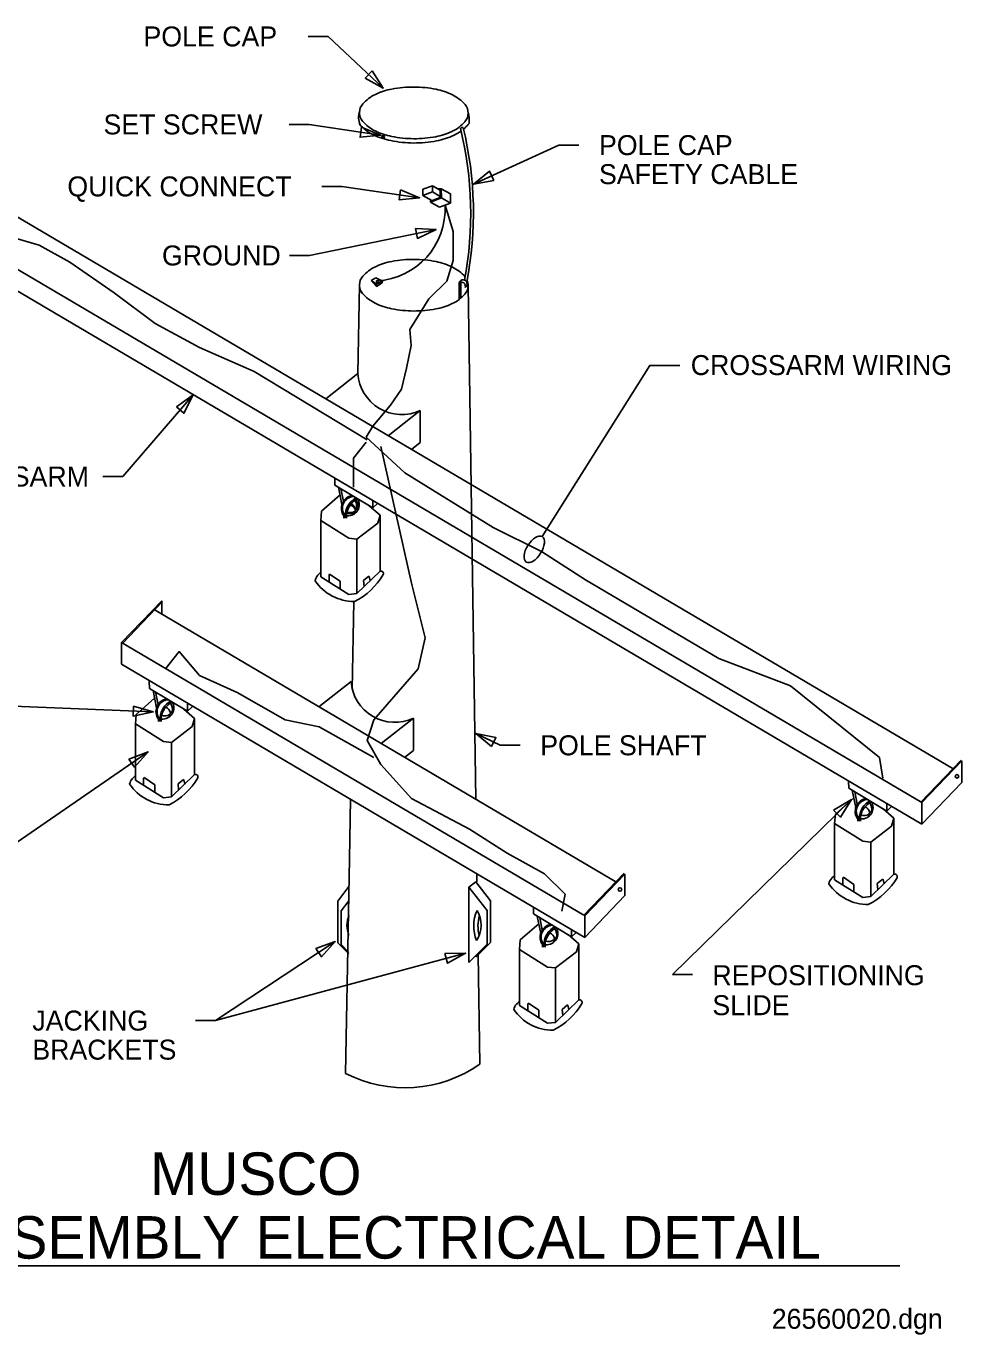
# Model space of a CAD drawing. Extents: x 10378 to 10425.2, y 10088.7 to 10132.4.
# Drawn here: x 10393.97 to 10425.18, y 10088.71 to 10132.38 of the extents above; entities that cross this region are included whole.
import ezdxf

# ---------------------------------------------------------------- set-up
doc = ezdxf.new("R2010")
doc.units = 0
for name, color, linetype in [('G-ANNO-TEXT', 7, 'Continuous'), ('G-DETL-LINE', 7, 'Continuous'), ('G-DETL-OTLN', 7, 'Continuous'), ('G-DETL-PATT', 7, 'Continuous')]:
    doc.layers.add(name, color=color, linetype=linetype)

msp = doc.modelspace()

# ---------------------------------------------------------------- linework, layer by layer
at = {"layer": 'G-ANNO-TEXT'}
for p, q in [((10403.381, 10132.033), (10404.048, 10132.033)), ((10404.048, 10132.033), (10405.885, 10130.313)), ((10402.741, 10129.099), (10403.408, 10129.099)), ((10403.408, 10129.099), (10405.796, 10128.737)), ((10411.744, 10128.407), (10408.893, 10127.106)), ((10412.411, 10128.407), (10411.744, 10128.407)), ((10403.834, 10127.03), (10404.501, 10127.03)), ((10404.501, 10127.03), (10407.097, 10126.652)), ((10403.427, 10124.727), (10407.645, 10125.592)), ((10402.76, 10124.727), (10403.427, 10124.727)), ((10397.193, 10117.35), (10399.546, 10120.075)), ((10396.526, 10117.35), (10397.193, 10117.35)), ((10391.793, 10109.759), (10398.213, 10109.494)), ((10409.785, 10108.382), (10408.966, 10108.778)), ((10410.452, 10108.382), (10409.785, 10108.382)), ((10393.168, 10104.808), (10398.04, 10108.165)), ((10415.527, 10100.733), (10421.497, 10106.57)), ((10400.289, 10099.197), (10404.282, 10101.835)), ((10400.289, 10099.197), (10408.629, 10101.444)), ((10416.194, 10100.733), (10415.527, 10100.733)), ((10399.622, 10099.197), (10400.289, 10099.197)), ((10399.622, 10099.197), (10400.289, 10099.197)), ((10380.467, 10091.02), (10423.113, 10091.02))]:
    msp.add_line(p, q, dxfattribs=at)
for points in [[(10405.512, 10130.891), (10405.885, 10130.313), (10405.284, 10130.647)], [(10405.161, 10129.002), (10405.796, 10128.737), (10405.112, 10128.672)], [(10409.569, 10127.231), (10408.893, 10127.106), (10409.43, 10127.535)], [(10406.462, 10126.913), (10407.097, 10126.652), (10406.413, 10126.583)], [(10406.959, 10125.621), (10407.645, 10125.592), (10407.025, 10125.295)], [(10398.984, 10119.68), (10399.546, 10120.075), (10399.236, 10119.462)], [(10397.554, 10109.688), (10398.213, 10109.494), (10397.54, 10109.355)], [(10409.494, 10108.338), (10408.966, 10108.778), (10409.639, 10108.638)], [(10397.397, 10107.924), (10398.04, 10108.165), (10397.586, 10107.649)], [(10420.903, 10106.223), (10421.497, 10106.57), (10421.136, 10105.985)], [(10403.634, 10101.607), (10404.282, 10101.835), (10403.818, 10101.329)], [(10407.941, 10101.431), (10408.629, 10101.444), (10408.028, 10101.11)]]:
    msp.add_lwpolyline(points, close=True, dxfattribs=at)
msp.add_lwpolyline([(10415.778, 10121.059), (10414.778, 10121.059), (10411.186, 10115.344)], dxfattribs=at)
msp.add_ellipse((10410.92, 10114.921), major_axis=(-0.266, -0.423), ratio=0.5, dxfattribs=at)
at = {"layer": 'G-DETL-LINE'}
for p, q in [((10407.521, 10127.05), (10407.202, 10126.936)), ((10407.781, 10126.902), (10407.521, 10127.05)), ((10407.521, 10126.845), (10407.521, 10127.05)), ((10407.202, 10126.936), (10407.202, 10126.731)), ((10407.521, 10126.845), (10407.202, 10126.731)), ((10407.506, 10126.557), (10407.202, 10126.731)), ((10407.456, 10126.538), (10407.783, 10126.661)), ((10407.456, 10126.509), (10407.821, 10126.647)), ((10407.456, 10126.509), (10407.456, 10126.586)), ((10407.783, 10126.695), (10407.521, 10126.845)), ((10407.679, 10126.951), (10407.818, 10126.951)), ((10407.783, 10126.661), (10407.78, 10126.951)), ((10408.122, 10126.777), (10407.818, 10126.951)), ((10407.821, 10126.647), (10407.818, 10126.951)), ((10408.126, 10126.473), (10407.821, 10126.647)), ((10408.122, 10126.777), (10408.126, 10126.473)), ((10407.76, 10126.335), (10407.456, 10126.509)), ((10408.126, 10126.473), (10407.76, 10126.335)), ((10405.485, 10123.888), (10405.63, 10123.978)), ((10405.63, 10123.978), (10405.853, 10123.866)), ((10405.652, 10123.688), (10405.485, 10123.888)), ((10405.652, 10123.766), (10405.485, 10123.888)), ((10405.853, 10123.866), (10405.652, 10123.766)), ((10405.652, 10123.688), (10405.842, 10123.81)), ((10405.652, 10123.766), (10405.652, 10123.688)), ((10405.842, 10123.81), (10405.853, 10123.866)), ((10404.265, 10117.292), (10404.27, 10117.063)), ((10404.27, 10117.063), (10405.54, 10116.301)), ((10404.39, 10116.991), (10404.506, 10116.416)), ((10404.473, 10116.941), (10404.557, 10116.526)), ((10404.441, 10116.738), (10403.827, 10116.2)), ((10405.54, 10116.301), (10405.54, 10116.539)), ((10403.827, 10116.2), (10403.8, 10115.879)), ((10404.624, 10116.106), (10404.66, 10116.118)), ((10404.624, 10115.961), (10404.624, 10116.106)), ((10404.66, 10115.961), (10404.66, 10116.118)), ((10405.778, 10116.066), (10405.418, 10116.373)), ((10405.54, 10116.301), (10405.694, 10116.448)), ((10405.698, 10115.798), (10405.778, 10116.066)), ((10405.778, 10116.066), (10405.778, 10114.193)), ((10403.8, 10115.879), (10403.8, 10114.006)), ((10403.8, 10115.879), (10404.736, 10115.29)), ((10404.57, 10116.034), (10404.606, 10116.046)), ((10404.57, 10115.961), (10404.57, 10116.034)), ((10404.606, 10115.961), (10404.606, 10116.046)), ((10405.003, 10115.263), (10405.698, 10115.798)), ((10404.736, 10115.29), (10405.003, 10115.263)), ((10405.003, 10115.263), (10405.003, 10113.444)), ((10403.8, 10114.006), (10404.736, 10113.418)), ((10404.095, 10114.09), (10404.074, 10114.066)), ((10404.074, 10113.834), (10404.074, 10114.066)), ((10404.095, 10114.09), (10404.446, 10113.854)), ((10405.778, 10114.193), (10405.003, 10113.444)), ((10405.224, 10113.879), (10405.404, 10114.029)), ((10405.243, 10113.685), (10405.224, 10113.879)), ((10405.404, 10114.029), (10405.415, 10114.019)), ((10405.415, 10114.019), (10405.448, 10113.874)), ((10404.446, 10113.603), (10404.446, 10113.854)), ((10405.003, 10113.444), (10404.736, 10113.418)), ((10398.079, 10110.507), (10398.084, 10110.279)), ((10398.255, 10109.953), (10397.641, 10109.415)), ((10398.084, 10110.279), (10399.354, 10109.517)), ((10398.204, 10110.207), (10398.32, 10109.632)), ((10398.287, 10110.157), (10398.371, 10109.741)), ((10399.592, 10109.281), (10399.232, 10109.589)), ((10399.354, 10109.517), (10399.354, 10109.755)), ((10399.354, 10109.517), (10399.508, 10109.664)), ((10397.641, 10109.415), (10397.614, 10109.094)), ((10397.614, 10109.094), (10398.55, 10108.506)), ((10397.614, 10109.094), (10397.614, 10107.222)), ((10398.384, 10109.25), (10398.42, 10109.261)), ((10398.384, 10109.176), (10398.384, 10109.25)), ((10398.42, 10109.176), (10398.42, 10109.261)), ((10398.438, 10109.321), (10398.473, 10109.333)), ((10398.438, 10109.176), (10398.438, 10109.321)), ((10398.473, 10109.176), (10398.473, 10109.333)), ((10399.512, 10109.014), (10399.592, 10109.281)), ((10399.592, 10109.281), (10399.592, 10107.409)), ((10398.817, 10108.479), (10399.512, 10109.014)), ((10398.55, 10108.506), (10398.817, 10108.479)), ((10398.817, 10108.479), (10398.817, 10106.66)), ((10399.592, 10107.409), (10398.817, 10106.66)), ((10397.614, 10107.222), (10398.55, 10106.633)), ((10397.909, 10107.306), (10397.888, 10107.281)), ((10397.888, 10107.049), (10397.888, 10107.281)), ((10397.909, 10107.306), (10398.26, 10107.069)), ((10398.26, 10106.818), (10398.26, 10107.069)), ((10399.038, 10107.095), (10399.218, 10107.244)), ((10399.057, 10106.901), (10399.038, 10107.095)), ((10399.218, 10107.244), (10399.229, 10107.234)), ((10399.229, 10107.234), (10399.261, 10107.09)), ((10421.403, 10107.181), (10421.408, 10106.953)), ((10421.408, 10106.953), (10422.678, 10106.19)), ((10398.817, 10106.66), (10398.55, 10106.633)), ((10421.579, 10106.627), (10420.965, 10106.089)), ((10421.527, 10106.881), (10421.644, 10106.305)), ((10421.611, 10106.831), (10421.695, 10106.415)), ((10420.965, 10106.089), (10420.938, 10105.768)), ((10422.916, 10105.955), (10422.556, 10106.263)), ((10422.678, 10106.19), (10422.678, 10106.429)), ((10422.678, 10106.19), (10422.832, 10106.338)), ((10420.938, 10105.768), (10420.938, 10103.896)), ((10420.938, 10105.768), (10421.874, 10105.179)), ((10421.708, 10105.923), (10421.744, 10105.935)), ((10421.708, 10105.85), (10421.708, 10105.923)), ((10421.744, 10105.85), (10421.744, 10105.935)), ((10421.762, 10105.995), (10421.797, 10106.007)), ((10421.762, 10105.85), (10421.762, 10105.995)), ((10421.797, 10105.85), (10421.797, 10106.007)), ((10422.141, 10105.153), (10422.836, 10105.688)), ((10422.836, 10105.688), (10422.916, 10105.955)), ((10422.916, 10105.955), (10422.916, 10104.083)), ((10421.874, 10105.179), (10422.141, 10105.153)), ((10422.141, 10105.153), (10422.141, 10103.334)), ((10420.938, 10103.896), (10421.874, 10103.307)), ((10421.233, 10103.98), (10421.212, 10103.955)), ((10421.212, 10103.723), (10421.212, 10103.955)), ((10421.233, 10103.98), (10421.584, 10103.743)), ((10422.916, 10104.083), (10422.141, 10103.334)), ((10422.362, 10103.768), (10422.542, 10103.918)), ((10422.542, 10103.918), (10422.553, 10103.908)), ((10422.553, 10103.908), (10422.585, 10103.763)), ((10404.736, 10103.667), (10404.364, 10103.181)), ((10408.742, 10103.653), (10408.97, 10103.828)), ((10408.742, 10103.653), (10409.344, 10102.868)), ((10408.742, 10101.14), (10408.742, 10103.653)), ((10408.97, 10103.828), (10409.458, 10103.191)), ((10421.584, 10103.492), (10421.584, 10103.743)), ((10422.381, 10103.575), (10422.362, 10103.768)), ((10404.364, 10103.181), (10404.364, 10101.793)), ((10404.736, 10103.195), (10404.478, 10102.858)), ((10409.458, 10103.191), (10409.458, 10101.803)), ((10410.892, 10102.983), (10410.897, 10102.755)), ((10422.141, 10103.334), (10421.874, 10103.307)), ((10404.478, 10102.858), (10404.478, 10101.733)), ((10409.344, 10102.868), (10409.344, 10101.742)), ((10410.897, 10102.755), (10412.167, 10101.992)), ((10411.017, 10102.683), (10411.134, 10102.107)), ((10411.1, 10102.633), (10411.185, 10102.217)), ((10411.068, 10102.429), (10410.454, 10101.891)), ((10412.167, 10101.992), (10412.167, 10102.231)), ((10412.167, 10101.992), (10412.321, 10102.14)), ((10404.364, 10101.793), (10404.736, 10101.421)), ((10404.478, 10101.733), (10404.736, 10101.474)), ((10409.344, 10101.742), (10408.742, 10101.14)), ((10409.458, 10101.803), (10408.97, 10101.315)), ((10410.454, 10101.891), (10410.427, 10101.57)), ((10411.197, 10101.725), (10411.233, 10101.737)), ((10411.197, 10101.652), (10411.197, 10101.725)), ((10411.233, 10101.652), (10411.233, 10101.737)), ((10411.251, 10101.797), (10411.287, 10101.809)), ((10411.251, 10101.652), (10411.251, 10101.797)), ((10411.287, 10101.652), (10411.287, 10101.809)), ((10412.405, 10101.757), (10412.045, 10102.065)), ((10412.325, 10101.49), (10412.405, 10101.757)), ((10412.405, 10101.757), (10412.405, 10099.885)), ((10410.427, 10101.57), (10410.427, 10099.698)), ((10410.427, 10101.57), (10411.363, 10100.982)), ((10411.63, 10100.955), (10412.325, 10101.49)), ((10411.363, 10100.982), (10411.63, 10100.955)), ((10411.63, 10100.955), (10411.63, 10099.136)), ((10410.427, 10099.698), (10411.363, 10099.109)), ((10410.723, 10099.782), (10410.701, 10099.757)), ((10410.701, 10099.525), (10410.701, 10099.757)), ((10410.723, 10099.782), (10411.073, 10099.545)), ((10411.073, 10099.294), (10411.073, 10099.545)), ((10412.405, 10099.885), (10411.63, 10099.136)), ((10411.851, 10099.57), (10412.031, 10099.72)), ((10411.87, 10099.377), (10411.851, 10099.57)), ((10412.031, 10099.72), (10412.043, 10099.71)), ((10412.043, 10099.71), (10412.075, 10099.565)), ((10411.63, 10099.136), (10411.363, 10099.109))]:
    msp.add_line(p, q, dxfattribs=at)
for centre, radius in [((10405.686, 10123.855), 0.0334), ((10425.018, 10107.347), 0.0592), ((10413.777, 10103.572), 0.0592)]:
    msp.add_circle(centre, radius, dxfattribs=at)
for centre, radius, start, end in [((10404.923, 10116.289), 0.436, 100.2717, 215.8313), ((10404.923, 10116.289), 0.4, 94.0056, 217.4608), ((10405.308, 10116.037), 0.688, 118.8543, 174.2368), ((10405.367, 10115.972), 0.722, 118.1089, 168.3754), ((10404.708, 10116.413), 0.375, 265.3953, 31.5556), ((10404.605, 10116.346), 0.395, 347.8326, 31.9067), ((10404.645, 10116.356), 0.395, 349.7008, 34.0489), ((10404.763, 10116.501), 0.356, 253.9647, 301.1435), ((10404.738, 10116.494), 0.382, 259.327, 302.5745), ((10404.69, 10116.131), 0.289, 20.663, 69.297), ((10404.694, 10116.186), 0.281, 12.7976, 63.9539), ((10405.076, 10116.162), 0.133, 95.1644, 192.366), ((10403.934, 10113.825), 0.328, 134.8398, 171.2692), ((10403.875, 10113.942), 0.207, 111.139, 146.0525), ((10403.878, 10115.265), 2.331, 296.6306, 329.3358), ((10405.803, 10114.11), 0.087, 337.3261, 106.4069), ((10404.912, 10114.752), 1.57, 213.9622, 270.399), ((10398.737, 10109.505), 0.436, 100.2717, 215.8313), ((10398.737, 10109.505), 0.4, 94.0056, 217.4608), ((10399.122, 10109.252), 0.688, 118.8543, 174.2368), ((10399.181, 10109.188), 0.722, 118.1089, 168.3754), ((10398.521, 10109.629), 0.375, 265.3953, 31.5556), ((10398.508, 10109.401), 0.281, 12.7976, 63.9539), ((10398.89, 10109.377), 0.133, 95.1644, 192.366), ((10398.459, 10109.571), 0.395, 349.7008, 34.0489), ((10398.577, 10109.716), 0.356, 253.9647, 301.1435), ((10397.689, 10107.157), 0.207, 111.139, 146.0525), ((10399.617, 10107.326), 0.087, 337.3261, 106.4069), ((10397.748, 10107.04), 0.328, 134.8398, 171.2692), ((10398.726, 10107.967), 1.57, 213.9622, 270.399), ((10397.692, 10108.481), 2.331, 296.6306, 329.3358), ((10422.061, 10106.178), 0.436, 100.2717, 215.8313), ((10422.061, 10106.178), 0.4, 94.0056, 217.4608), ((10422.446, 10105.926), 0.688, 118.8543, 174.2368), ((10422.505, 10105.862), 0.722, 118.1089, 168.3754), ((10421.845, 10106.302), 0.375, 265.3953, 31.5556), ((10421.783, 10106.245), 0.395, 349.7008, 34.0489), ((10421.901, 10106.39), 0.356, 253.9647, 301.1435), ((10421.832, 10106.075), 0.281, 12.7976, 63.9539), ((10422.214, 10106.051), 0.133, 95.1644, 192.366), ((10421.072, 10103.714), 0.328, 134.8398, 171.2692), ((10421.013, 10103.831), 0.207, 111.139, 146.0525), ((10421.016, 10105.154), 2.331, 296.6306, 329.3358), ((10422.941, 10103.999), 0.087, 337.3261, 106.4069), ((10422.05, 10104.641), 1.57, 213.9622, 270.399), ((10405.617, 10102.373), 0.945, 158.9471, 201.0529), ((10403.643, 10102.34), 1.136, 15.9016, 17.6825), ((10410.178, 10102.35), 1.279, 155.8022, 202.2608), ((10408.204, 10102.383), 0.945, 326.7536, 31.3094), ((10410.178, 10102.35), 1.136, 162.3175, 195.7456), ((10411.55, 10101.98), 0.436, 100.2717, 215.8313), ((10411.55, 10101.98), 0.4, 94.0056, 217.4608), ((10411.935, 10101.728), 0.688, 118.8543, 174.2368), ((10411.994, 10101.664), 0.722, 118.1089, 168.3754), ((10411.335, 10102.104), 0.375, 265.3953, 31.5556), ((10411.321, 10101.877), 0.281, 12.7976, 63.9539), ((10411.272, 10102.047), 0.395, 349.7008, 34.0489), ((10411.39, 10102.192), 0.356, 253.9647, 301.1435), ((10411.704, 10101.853), 0.133, 95.1644, 192.366), ((10410.562, 10099.516), 0.328, 134.8398, 171.2692), ((10411.539, 10100.443), 1.57, 213.9622, 270.399), ((10410.502, 10099.633), 0.207, 111.139, 149.3316), ((10410.505, 10100.957), 2.331, 296.6306, 329.3358), ((10412.43, 10099.801), 0.087, 337.3261, 106.4069)]:
    msp.add_arc(centre, radius, start, end, dxfattribs=at)
at = {"layer": 'G-DETL-OTLN'}
for p, q in [((10405.876, 10128.642), (10405.876, 10128.733)), ((10405.885, 10128.645), (10405.885, 10128.736)), ((10391.182, 10127.479), (10424.91, 10107.581)), ((10390.083, 10126.387), (10423.843, 10106.471)), ((10390.083, 10125.666), (10423.843, 10105.749)), ((10405.037, 10120.784), (10405.089, 10123.745)), ((10408.417, 10123.815), (10408.472, 10123.893)), ((10408.417, 10123.261), (10408.417, 10123.815)), ((10408.472, 10123.305), (10408.472, 10123.835)), ((10408.617, 10123.659), (10408.673, 10123.737)), ((10408.969, 10106.579), (10408.716, 10123.725)), ((10405.037, 10120.784), (10403.963, 10119.939)), ((10407.117, 10119.557), (10406.043, 10118.712)), ((10407.117, 10119.557), (10407.117, 10118.482)), ((10407.117, 10118.482), (10406.824, 10118.251)), ((10397.156, 10111.808), (10398.494, 10113.2)), ((10397.182, 10111.783), (10398.519, 10113.175)), ((10398.494, 10113.2), (10398.494, 10112.759)), ((10404.851, 10110.245), (10404.903, 10113.182)), ((10398.219, 10112.921), (10413.638, 10103.825)), ((10397.156, 10111.808), (10397.156, 10111.086)), ((10397.156, 10111.808), (10412.571, 10102.714)), ((10397.156, 10111.086), (10412.602, 10101.974)), ((10404.808, 10110.512), (10403.734, 10109.668)), ((10406.888, 10109.285), (10405.814, 10108.44)), ((10406.888, 10109.285), (10406.888, 10108.21)), ((10406.888, 10108.21), (10406.595, 10107.98)), ((10423.811, 10106.489), (10425.154, 10107.887)), ((10423.843, 10106.471), (10425.18, 10107.863)), ((10425.18, 10107.863), (10425.18, 10107.141)), ((10423.843, 10105.749), (10425.18, 10107.141)), ((10404.752, 10104.593), (10404.787, 10106.585)), ((10423.843, 10106.471), (10423.843, 10105.749)), ((10404.626, 10097.434), (10404.752, 10104.593)), ((10409.009, 10103.828), (10409.006, 10104.096)), ((10412.571, 10102.714), (10413.914, 10104.112)), ((10412.602, 10102.695), (10413.94, 10104.087)), ((10413.94, 10104.087), (10413.94, 10103.366)), ((10412.602, 10101.974), (10413.94, 10103.366)), ((10412.602, 10102.695), (10412.602, 10101.974)), ((10409.099, 10097.744), (10409.045, 10101.39))]:
    msp.add_line(p, q, dxfattribs=at)
msp.add_circle((10405.882, 10128.688), 0.0455, dxfattribs=at)
for centre, radius, start, end in [((10406.176, 10128.92), 1.303, 115.1068, 138.6129), ((10406.607, 10128.001), 2.319, 100.8241, 115.1068), ((10406.887, 10126.54), 3.806, 89.6877, 100.8241), ((10406.887, 10126.54), 3.806, 78.5514, 89.6877), ((10407.182, 10127.998), 2.319, 64.2687, 78.5514), ((10407.623, 10128.912), 1.303, 40.7626, 64.2687), ((10405.528, 10129.491), 0.439, 138.6129, 179.6877), ((10408.277, 10129.476), 0.439, 359.6877, 40.7626), ((10405.756, 10129.34), 0.694, 163.3529, 201.6942), ((10405.528, 10129.491), 0.439, 179.6877, 220.7626), ((10406.183, 10130.055), 1.303, 220.7626, 244.2687), ((10407.629, 10130.048), 1.303, 295.1068, 318.6129), ((10408.277, 10129.476), 0.439, 318.6129, 359.6877), ((10407.639, 10129.229), 1.11, 354.6742, 14.364), ((10406.183, 10130.055), 1.447, 220.7626, 244.2687), ((10406.623, 10130.97), 2.462, 244.2687, 258.5514), ((10406.623, 10130.97), 2.319, 244.2687, 258.5514), ((10407.198, 10130.967), 2.319, 280.8241, 295.1068), ((10407.198, 10130.967), 2.462, 280.8241, 295.1068), ((10407.629, 10130.048), 1.447, 295.1068, 306.0196), ((10408.522, 10128.905), 0.0895, 72.3491, 135.7413), ((10396.772, 10126.118), 12.028, 349.3877, 13.7065), ((10396.863, 10126.14), 12.028, 348.9395, 13.7065), ((10407.629, 10130.048), 1.447, 310.1185, 318.6129), ((10408.277, 10129.476), 0.583, 318.6129, 323.3443), ((10406.919, 10132.428), 3.95, 258.5514, 269.6877), ((10406.919, 10132.428), 3.806, 258.5514, 269.6877), ((10406.919, 10132.428), 3.95, 269.6877, 280.8241), ((10406.919, 10132.428), 3.806, 269.6877, 280.8241), ((10406.607, 10122.252), 2.319, 100.8241, 115.1068), ((10406.887, 10120.791), 3.806, 89.6877, 100.8241), ((10406.887, 10120.791), 3.806, 78.5514, 89.6877), ((10407.182, 10122.249), 2.319, 64.2687, 78.5514), ((10405.528, 10123.742), 0.439, 138.6129, 179.6877), ((10406.176, 10123.171), 1.303, 115.1068, 138.6129), ((10407.623, 10123.163), 1.303, 40.7626, 64.2687), ((10408.277, 10123.727), 0.439, 39.8709, 40.7626), ((10405.528, 10123.742), 0.439, 179.6877, 220.7626), ((10408.489, 10123.701), 0.135, 341.8936, 122.3019), ((10408.545, 10123.779), 0.135, 341.8936, 122.3019), ((10408.277, 10123.727), 0.439, 318.6129, 359.6877), ((10408.277, 10123.727), 0.439, 359.6877, 23.1028), ((10406.183, 10124.307), 1.303, 220.7626, 244.2687), ((10406.623, 10125.221), 2.319, 244.2687, 258.5514), ((10407.198, 10125.218), 2.319, 280.8241, 295.1068), ((10407.629, 10124.299), 1.303, 295.1068, 318.6129), ((10406.919, 10126.679), 3.806, 258.5514, 269.6877), ((10406.919, 10126.679), 3.806, 269.6877, 280.8241), ((10406.498, 10120.885), 1.465, 183.9415, 294.9806), ((10406.27, 10110.613), 1.465, 183.9415, 294.9806), ((10406.606, 10101.295), 4.339, 242.8489, 305.0763)]:
    msp.add_arc(centre, radius, start, end, dxfattribs=at)
at = {"layer": 'G-DETL-PATT'}
for points in [[(10407.943, 10126.404), (10408.212, 10125.529), (10408.212, 10124.563), (10407.998, 10123.865), (10407.408, 10123.275), (10406.764, 10122.255), (10406.818, 10121.718), (10406.657, 10120.967), (10406.496, 10120.269), (10406.121, 10119.733), (10405.531, 10119.035), (10405.316, 10118.659), (10406.603, 10117.478), (10409.553, 10115.654), (10411.162, 10114.849)], [(10405.342, 10118.577), (10401.582, 10120.857), (10399.759, 10121.655), (10398.278, 10122.453), (10396.911, 10123.479), (10395.43, 10124.505), (10394.404, 10125.075), (10393.607, 10125.303), (10393.151, 10125.417), (10392.354, 10125.417), (10392.012, 10125.303)], [(10405.316, 10118.498), (10404.887, 10117.961), (10404.887, 10117.478), (10404.887, 10116.995)], [(10405.798, 10118.349), (10406.823, 10113.789), (10407.279, 10111.965), (10407.051, 10110.939), (10405.57, 10109.229), (10405.342, 10108.545), (10405.798, 10107.747), (10406.823, 10106.607), (10408.76, 10105.581), (10410.013, 10104.783), (10411.266, 10104.099), (10411.95, 10103.415), (10411.836, 10102.845)], [(10411.162, 10114.849), (10412.633, 10113.903), (10417.077, 10111.281), (10419.469, 10110.369), (10422.432, 10107.975), (10422.546, 10107.291)], [(10405.57, 10107.975), (10403.747, 10109.001), (10402.607, 10109.229), (10401.012, 10110.141), (10399.759, 10110.711), (10399.076, 10111.509), (10398.62, 10110.939)]]:
    msp.add_lwpolyline(points, dxfattribs=at)
msp.add_arc((10405.543, 10126.279), 2.403, 273.178, 2.9796, dxfattribs=at)

# ---------------------------------------------------------------- texts
at = {"layer": 'G-ANNO-TEXT'}
for s, height, p in [('POLE CAP', 0.6667, (10397.885, 10131.7)), ('SET SCREW', 0.6667, (10396.552, 10128.765)), ('POLE CAP ', 0.6667, (10413.078, 10128.074)), ('SAFETY CABLE', 0.66667, (10413.078, 10127.106)), ('QUICK CONNECT', 0.66667, (10395.346, 10126.696)), ('GROUND', 0.6667, (10398.503, 10124.393)), ('CROSSARM WIRING', 0.66667, (10416.139, 10120.735)), ('CROSSARM', 0.6667, (10390.915, 10117.017)), ('POLE SHAFT', 0.6667, (10411.118, 10108.049)), ('REPOSITIONING', 0.66667, (10416.86, 10100.378)), ('SLIDE', 0.6667, (10416.86, 10099.378)), ('JACKING ', 0.6667, (10394.178, 10098.864)), ('BRACKETS', 0.6667, (10394.178, 10097.895)), ('MUSCO', 1.4167, (10398.106, 10093.381)), ('POLE TOP ASSEMBLY ELECTRICAL DETAIL', 1.41667, (10380.89, 10091.256)), ('26560020.dgn', 0.66667, (10418.841, 10088.914))]:
    msp.add_text(s, height=height, dxfattribs=at).set_placement(p)

doc.saveas('drawing.dxf')
